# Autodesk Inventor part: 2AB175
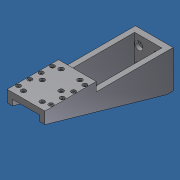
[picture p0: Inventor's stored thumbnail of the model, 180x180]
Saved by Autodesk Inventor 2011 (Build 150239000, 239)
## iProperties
Created: 2012-05
Part Number: 2AB175
Document SubType Name: Modeling
Designer: ramunas
Density: 1 g/cm^3
Author: ramunas
Translation Standard: STEP AP203
FileName: 2AB175.STEP
PreProcessor: SolidWorks 2003240
PostProcessor: Build: 239, Release: 2011 RTM - Date: Wed 02/17/2010
Sent Units: millimeter
Uncertainty: 1e-05
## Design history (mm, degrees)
feature "Base1"
node "NONE"
